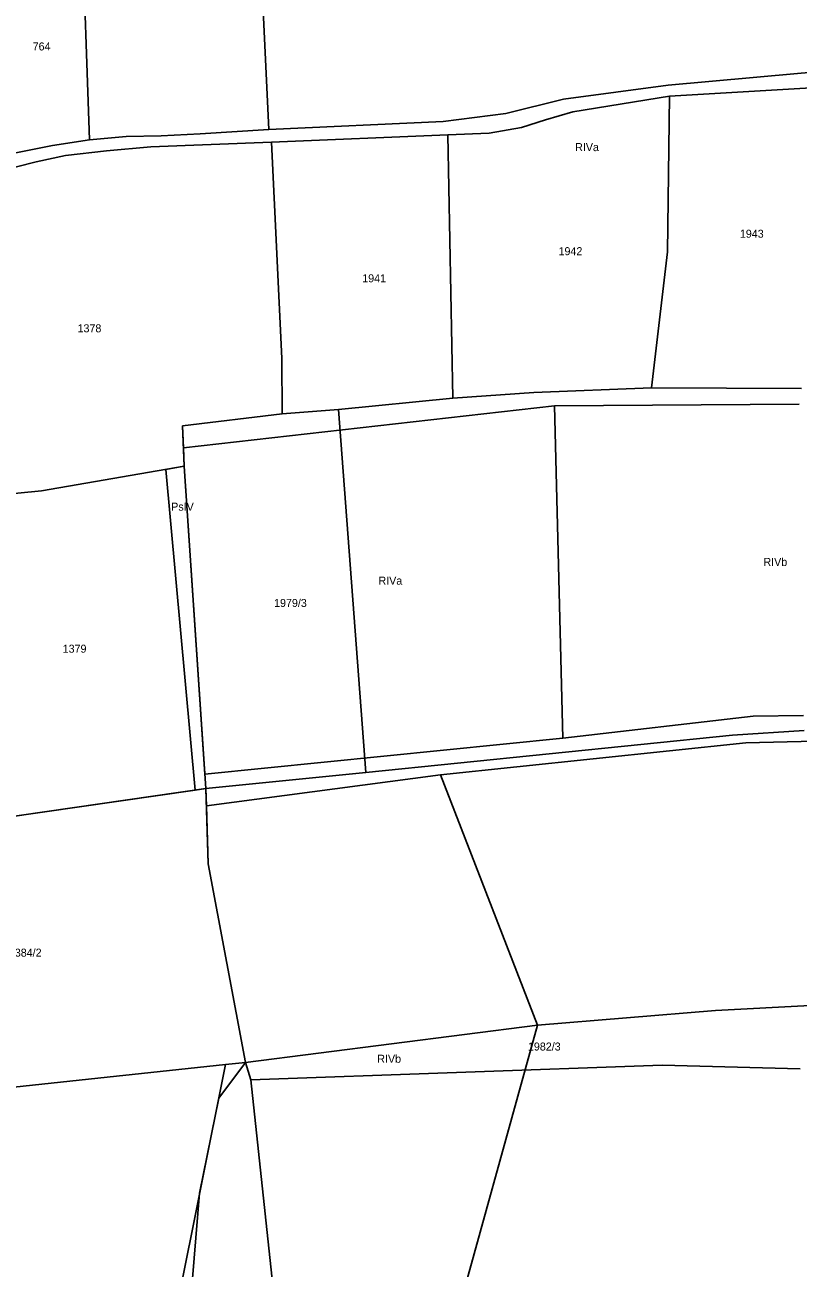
# Model space of a CAD drawing. Extents: x 7498273 to 7499989, y 5499795 to 5500810.
# Drawn here: x 7498893.9 to 7499038.9, y 5499981.8 to 5500214.9 of the extents above; entities that cross this region are included whole.
import ezdxf

# ---------------------------------------------------------------- set-up
doc = ezdxf.new("R2010")
doc.units = 0
for name, color, linetype in [('209-oznaczenie konturu klasyfikacyjnego', 7, 'Continuous'), ('211-numer działki ewidencyjnej', 7, 'Continuous'), ('217-kontur klasyfikacyjny', 7, 'Continuous'), ('218-kontur użytku gruntowego', 7, 'Continuous'), ('219-działka ewidencyjna', 7, 'Continuous')]:
    doc.layers.add(name, color=color, linetype=linetype)

msp = doc.modelspace()

# ---------------------------------------------------------------- linework, layer by layer
at = {"layer": '217-kontur klasyfikacyjny'}
for points in [[(7498906.02, 5500193.33), (7498904.55, 5500234.65)], [(7499057.33, 5500207.41), (7499038.75, 5500205.74)], [(7499038.75, 5500205.74), (7499014.53, 5500203.6)], [(7499014.53, 5500203.6), (7498994.86, 5500200.96)], [(7499014.74, 5500201.49), (7499044.53, 5500203.27)], [(7498994.86, 5500200.96), (7498984.06, 5500198.27)], [(7498996.64, 5500198.6), (7499014.74, 5500201.49)], [(7498984.06, 5500198.27), (7498972.3, 5500196.78)], [(7498991.49, 5500197.07), (7498996.64, 5500198.6)], [(7498972.3, 5500196.78), (7498939.66, 5500195.3)], [(7498980.93, 5500194.61), (7498987.03, 5500195.63)], [(7498987.03, 5500195.63), (7498991.49, 5500197.07)], [(7498899.09, 5500192.25), (7498906.02, 5500193.33)], [(7498912.87, 5500193.98), (7498906.02, 5500193.33)], [(7498919.47, 5500194.11), (7498912.87, 5500193.98)], [(7498926.78, 5500194.48), (7498919.47, 5500194.11)], [(7498939.66, 5500195.3), (7498926.78, 5500194.48)], [(7498940.14, 5500192.88), (7498973.17, 5500194.26)], [(7498973.17, 5500194.26), (7498980.93, 5500194.61)], [(7498891.57, 5500190.8), (7498899.09, 5500192.25)], [(7498901.5, 5500190.4), (7498909.18, 5500191.25)], [(7498909.18, 5500191.25), (7498917.54, 5500192.02)], [(7498917.54, 5500192.02), (7498940.14, 5500192.88)], [(7498888.55, 5500187.34), (7498896.01, 5500189.2)], [(7498896.01, 5500189.2), (7498901.5, 5500190.4)], [(7499011.39, 5500146.84), (7498989.34, 5500145.94)], [(7499039.49, 5500146.69), (7499011.39, 5500146.84)], [(7498974.16, 5500144.93), (7498952.7, 5500142.79)], [(7498989.34, 5500145.94), (7498974.16, 5500144.93)], [(7498942.12, 5500141.97), (7498923.42, 5500139.74)], [(7498923.62, 5500135.6), (7498993.23, 5500143.46)], [(7498952.7, 5500142.79), (7498942.12, 5500141.97)], [(7498993.23, 5500143.46), (7499039.1, 5500143.76)], [(7498994.77, 5500081.14), (7498993.23, 5500143.46)], [(7498923.42, 5500139.74), (7498923.62, 5500135.6)], [(7498923.62, 5500135.6), (7498923.79, 5500132.14)], [(7498923.79, 5500132.14), (7498920.33, 5500131.55)], [(7498920.33, 5500131.55), (7498925.81, 5500071.43)], [(7498927.63, 5500074.42), (7498923.79, 5500132.14)], [(7499030.44, 5500085.3), (7498994.77, 5500081.14)], [(7499039.89, 5500085.43), (7499030.44, 5500085.3)], [(7499029.08, 5500080.27), (7499073.14, 5500081.34)], [(7498994.77, 5500081.14), (7498927.63, 5500074.42)], [(7498971.84, 5500074.29), (7499029.08, 5500080.27)], [(7498927.92, 5500068.49), (7498971.84, 5500074.29)], [(7498990.01, 5500027.36), (7498971.84, 5500074.29)], [(7498925.81, 5500071.43), (7498882.83, 5500065.22)], [(7498925.81, 5500071.43), (7498927.81, 5500071.72)], [(7498927.81, 5500071.72), (7498927.92, 5500068.49)], [(7498927.92, 5500068.49), (7498928.29, 5500057.59)], [(7498928.29, 5500057.59), (7498935.27, 5500020.35)], [(7498973.34, 5499967.13), (7498990.01, 5500027.36)], [(7498935.27, 5500020.35), (7498930.25, 5500013.66)], [(7498936.29, 5500017.13), (7498935.27, 5500020.35)], [(7498940.39, 5499978.56), (7498936.29, 5500017.13)], [(7498930.25, 5500013.66), (7498926.66, 5499995.83)], [(7498926.66, 5499995.83), (7498924.96, 5499975.32)]]:
    msp.add_lwpolyline(points, dxfattribs=at)
at = {"layer": '218-kontur użytku gruntowego'}
for points in [[(7498906.02, 5500193.33), (7498904.55, 5500234.65)], [(7499057.33, 5500207.41), (7499038.75, 5500205.74)], [(7499038.75, 5500205.74), (7499014.53, 5500203.6)], [(7499014.53, 5500203.6), (7498994.86, 5500200.96)], [(7499014.74, 5500201.49), (7499044.53, 5500203.27)], [(7498994.86, 5500200.96), (7498984.06, 5500198.27)], [(7498996.64, 5500198.6), (7499014.74, 5500201.49)], [(7498984.06, 5500198.27), (7498972.3, 5500196.78)], [(7498991.49, 5500197.07), (7498996.64, 5500198.6)], [(7498972.3, 5500196.78), (7498939.66, 5500195.3)], [(7498980.93, 5500194.61), (7498987.03, 5500195.63)], [(7498987.03, 5500195.63), (7498991.49, 5500197.07)], [(7498899.09, 5500192.25), (7498906.02, 5500193.33)], [(7498912.87, 5500193.98), (7498906.02, 5500193.33)], [(7498919.47, 5500194.11), (7498912.87, 5500193.98)], [(7498926.78, 5500194.48), (7498919.47, 5500194.11)], [(7498939.66, 5500195.3), (7498926.78, 5500194.48)], [(7498940.14, 5500192.88), (7498973.17, 5500194.26)], [(7498973.17, 5500194.26), (7498980.93, 5500194.61)], [(7498891.57, 5500190.8), (7498899.09, 5500192.25)], [(7498901.5, 5500190.4), (7498909.18, 5500191.25)], [(7498909.18, 5500191.25), (7498917.54, 5500192.02)], [(7498917.54, 5500192.02), (7498940.14, 5500192.88)], [(7498888.55, 5500187.34), (7498896.01, 5500189.2)], [(7498896.01, 5500189.2), (7498901.5, 5500190.4)], [(7499011.39, 5500146.84), (7498989.34, 5500145.94)], [(7499039.49, 5500146.69), (7499011.39, 5500146.84)], [(7498974.16, 5500144.93), (7498952.7, 5500142.79)], [(7498989.34, 5500145.94), (7498974.16, 5500144.93)], [(7498942.12, 5500141.97), (7498923.42, 5500139.74)], [(7498923.62, 5500135.6), (7498993.23, 5500143.46)], [(7498952.7, 5500142.79), (7498942.12, 5500141.97)], [(7499039.1, 5500143.76), (7498993.23, 5500143.46)], [(7498993.23, 5500143.46), (7498994.77, 5500081.14)], [(7498923.42, 5500139.74), (7498923.62, 5500135.6)], [(7498923.62, 5500135.6), (7498923.79, 5500132.14)], [(7498923.79, 5500132.14), (7498920.33, 5500131.55)], [(7498920.33, 5500131.55), (7498925.81, 5500071.43)], [(7498923.79, 5500132.14), (7498927.63, 5500074.42)], [(7498994.77, 5500081.14), (7499030.44, 5500085.3)], [(7499030.44, 5500085.3), (7499039.89, 5500085.43)], [(7499073.14, 5500081.34), (7499029.08, 5500080.27)], [(7498927.63, 5500074.42), (7498994.77, 5500081.14)], [(7499029.08, 5500080.27), (7498971.84, 5500074.29)], [(7498971.84, 5500074.29), (7498927.92, 5500068.49)], [(7498971.84, 5500074.29), (7498990.01, 5500027.36)], [(7498925.81, 5500071.43), (7498882.83, 5500065.22)], [(7498925.81, 5500071.43), (7498927.81, 5500071.72)], [(7498927.81, 5500071.72), (7498927.92, 5500068.49)], [(7498927.92, 5500068.49), (7498928.29, 5500057.59)], [(7498928.29, 5500057.59), (7498935.27, 5500020.35)], [(7498990.01, 5500027.36), (7498973.34, 5499967.13)], [(7498935.27, 5500020.35), (7498930.25, 5500013.66)], [(7498935.27, 5500020.35), (7498936.29, 5500017.13)], [(7498936.29, 5500017.13), (7498940.39, 5499978.56)], [(7498930.25, 5500013.66), (7498926.66, 5499995.83)], [(7498926.66, 5499995.83), (7498924.96, 5499975.32)]]:
    msp.add_lwpolyline(points, dxfattribs=at)
at = {"layer": '219-działka ewidencyjna'}
for points in [[(7498937.55, 5500238.59), (7498939.66, 5500195.3)], [(7499038.75, 5500205.74), (7499057.33, 5500207.41)], [(7499014.53, 5500203.6), (7499038.75, 5500205.74)], [(7498994.86, 5500200.96), (7499014.53, 5500203.6)], [(7499014.74, 5500201.49), (7499044.53, 5500203.27)], [(7498994.86, 5500200.96), (7498984.06, 5500198.27)], [(7498996.64, 5500198.6), (7499014.74, 5500201.49)], [(7499014.38, 5500172.32), (7499014.74, 5500201.49)], [(7498972.3, 5500196.78), (7498984.06, 5500198.27)], [(7498991.49, 5500197.07), (7498996.64, 5500198.6)], [(7498939.66, 5500195.3), (7498972.3, 5500196.78)], [(7498980.93, 5500194.61), (7498987.03, 5500195.63)], [(7498987.03, 5500195.63), (7498991.49, 5500197.07)], [(7498899.09, 5500192.25), (7498906.02, 5500193.33)], [(7498906.02, 5500193.33), (7498912.87, 5500193.98)], [(7498912.87, 5500193.98), (7498919.47, 5500194.11)], [(7498919.47, 5500194.11), (7498926.78, 5500194.48)], [(7498926.78, 5500194.48), (7498939.66, 5500195.3)], [(7498940.14, 5500192.88), (7498973.17, 5500194.26)], [(7498973.17, 5500194.26), (7498980.93, 5500194.61)], [(7498973.17, 5500194.26), (7498974.16, 5500144.93)], [(7498891.57, 5500190.8), (7498899.09, 5500192.25)], [(7498901.5, 5500190.4), (7498909.18, 5500191.25)], [(7498909.18, 5500191.25), (7498917.54, 5500192.02)], [(7498917.54, 5500192.02), (7498940.14, 5500192.88)], [(7498940.14, 5500192.88), (7498942.1, 5500152.34)], [(7498888.55, 5500187.34), (7498896.01, 5500189.2)], [(7498896.01, 5500189.2), (7498901.5, 5500190.4)], [(7499011.39, 5500146.84), (7499014.38, 5500172.32)], [(7498942.1, 5500152.34), (7498942.12, 5500141.97)], [(7498989.34, 5500145.94), (7499011.39, 5500146.84)], [(7499011.39, 5500146.84), (7499039.49, 5500146.69)], [(7498952.7, 5500142.79), (7498974.16, 5500144.93)], [(7498974.16, 5500144.93), (7498989.34, 5500145.94)], [(7498923.42, 5500139.74), (7498942.12, 5500141.97)], [(7498942.12, 5500141.97), (7498952.7, 5500142.79)], [(7498952.7, 5500142.79), (7498957.82, 5500074.72)], [(7498923.42, 5500139.74), (7498923.79, 5500132.14)], [(7498897.02, 5500127.56), (7498923.79, 5500132.14)], [(7498923.79, 5500132.14), (7498927.81, 5500071.72)], [(7498874.15, 5500125.26), (7498897.02, 5500127.56)], [(7499026.6, 5500081.75), (7498957.82, 5500074.72)], [(7499026.6, 5500081.75), (7499039.99, 5500082.58)], [(7498927.81, 5500071.72), (7498957.82, 5500074.72)], [(7498882.83, 5500065.22), (7498927.81, 5500071.72)], [(7498927.81, 5500071.72), (7498928.29, 5500057.59)], [(7498928.29, 5500057.59), (7498935.27, 5500020.35)], [(7498990.01, 5500027.36), (7499023.4, 5500030.13)], [(7499023.4, 5500030.13), (7499041.16, 5500031.06)], [(7498935.27, 5500020.35), (7498990.01, 5500027.36)], [(7498853.81, 5500011.67), (7498931.52, 5500019.99)], [(7498922.42, 5499974.79), (7498931.52, 5500019.99)], [(7498931.52, 5500019.99), (7498935.27, 5500020.35)], [(7498935.27, 5500020.35), (7498936.29, 5500017.13)], [(7498936.29, 5500017.13), (7499013.38, 5500019.83)], [(7499013.38, 5500019.83), (7499039.25, 5500019.15)]]:
    msp.add_lwpolyline(points, dxfattribs=at)

# ---------------------------------------------------------------- texts
at = {"layer": '209-oznaczenie konturu klasyfikacyjnego'}
for s, p in [('RIVa', (7498997.07, 5500191.22)), ('PsIV', (7498921.33, 5500123.81)), ('RIVb', (7499032.38, 5500113.45)), ('RIVa', (7498960.2, 5500109.94)), ('RIVb', (7498959.97, 5500020.31))]:
    msp.add_text(s, height=1.5, dxfattribs=at).set_placement(p)
at = {"layer": '211-numer działki ewidencyjnej'}
for s, p in [('764', (7498895.35, 5500210.09)), ('1943', (7499027.96, 5500174.98)), ('1942', (7498993.96, 5500171.71)), ('1941', (7498957.15, 5500166.62)), ('1378', (7498903.77, 5500157.25)), ('1979/3', (7498940.62, 5500105.76)), ('1379', (7498900.98, 5500097.18)), ('1384/2', (7498890.89, 5500040.2)), ('1982/3', (7498988.22, 5500022.6))]:
    msp.add_text(s, height=1.5, dxfattribs=at).set_placement(p)

doc.saveas('drawing.dxf')
